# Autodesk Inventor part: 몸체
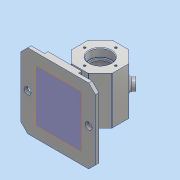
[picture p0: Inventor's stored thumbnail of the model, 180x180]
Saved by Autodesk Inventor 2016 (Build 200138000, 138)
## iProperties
Created: 2018-06
Part Number: 몸체
Material: 알루미늄 6061
Document SubType Name: Modeling
Designer: 605-11
Density: 2.7 g/cm^3
Appearance: 알루미늄 - 평지
Author: 605-11
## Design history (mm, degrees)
sketch "스케치1"
  geometry: L1 (30, -12.426)-(12.426, -30); L2 (12.426, -30)-(-12.426, -30); L3 (-12.426, -30)-(-30, -12.426); L4 (-30, -12.426)-(-30, 12.426); L5 (-30, 12.426)-(-12.426, 30); L6 (-12.426, 30)-(12.426, 30); L7 (12.426, 30)-(30, 12.426); L8 (30, 12.426)-(30, -12.426); L9 (0, 0)-(-12.426, 30); L10 (0, 0)-(0, 30); L11 (0, 0)-(12.426, 30); 1 further point
  constraints: 22 end point, 2 point on line, 1 coincident, 1 midpoint, 1 vertical, 1 vertical alignment, 17 other
  dimensions: "d0" = 60 distance between parallel lines of L8 L4; "d1" = 22.5 deg angle of L10 L9; "d2" = 45 deg angle of L11 L9
extrude "돌출1" new body sketch "스케치1" stored distance "d3" = 70; taper "d4" = 0 deg
sketch "스케치2"
  geometry: L1 (0, 35)-(16, 35); L2 (16, 35)-(16, 23.3); L3 (15.7, 23)-(0, 23); L4 (0, 23)-(0, 35); L5 (0, 23)-(14, 23); L6 (14, 23)-(14, 20); L7 (14, 20)-(0, 20); L8 (0, 20)-(0, 23); L9 (0, 20)-(22, 20); L10 (25, 17)-(25, -17); L11 (22, -20)-(0, -20); L12 (0, -20)-(0, 20); L13 (0, -20)-(14, -20); L14 (14, -20)-(14, -23); L15 (14, -23)-(0, -23); L16 (0, -23)-(0, -20); L17 (0, -23)-(15.7, -23); L18 (16, -23.3)-(16, -35); L19 (16, -35)-(0, -35); L20 (0, -35)-(0, -23); L21 (12.426, 35)-(-12.426, 35) reference; A1 r 0.3 centre (15.7, 23.3) between (15.7, 23) and (16, 23.3); A2 r 0.3 centre (15.7, -23.3) between (16, -23.3) and (15.7, -23); A3 r 3 centre (22, -17) between (22, -20) and (25, -17); A4 r 3 centre (22, 17) between (25, 17) and (22, 20); 6 further points
  constraints: 40 end point, 10 parallel, 8 point on circle, 8 point on line, 8 tangent, 5 horizontal, 5 perpendicular, 4 centre point, 2 equal radius, 1 coincident, 1 midpoint
  dimensions: "d5" = 12 distance of L1.end point (16, 23); "d6" = 16 distance of L1.start L1.end; "d7" = 3 distance of L5.end L6.end; "d8" = 14 distance of L3.end L5.end; "d9" = 40 distance of point (25, 20) point (25, -20); "d10" = 25 distance of L7.end point (25, 20); "d11" = 3 distance of L13.end L14.end; "d12" = 14 distance of L11.end L13.end; "d13" = 12 distance of point (16, -23) L18.end; "d14" = 16 distance of L15.end point (16, -23); "d15" = 0.3 radius of A1; "d16" = 3 radius of A3
revolve "회전1" sketch "스케치2" stored, may be unused: angle "d17" = 90 deg
chamfer "모따기1" distance "d18" = 1; stored, may be unused: second distance "d19" = 2, angle "d20" = 45 deg
sketch "스케치3"
  geometry: L1 (-24.853, 70)-(0, 70) reference; C1 r 8 at (-12.426, 35); 2 further points
  constraints: 1 centre point, 1 midpoint, 1 vertical alignment
  dimensions: "d21" = 35 distance from line of L1 C1.centre; "d22" = 16 diameter of C1
extrude "돌출2" join sketch "스케치3" distance "d23" = 7; taper "d24" = 0 deg
fillet "모깎기1" dims "d25" = 3
sketch "스케치4"
  geometry: C1 r 4 at (0, 0); 1 further point
  constraints: 1 centre point, 1 coincident
  dimensions: "d26" = 8 diameter of C1
extrude "돌출3" cut sketch "스케치4" stored distance "d27" = 7; taper "d28" = 0 deg; dims "d5" = 12, "d6" = 16, "d7" = 3, "d8" = 14, "d9" = 40, "d10" = 25, "d11" = 3, "d12" = 14, "d13" = 12, "d14" = 16, "d15" = 0.3, "d16" = 3, "d31" = 45 deg
chamfer "모따기2" distance "d29" = 1; stored, may be unused: second distance "d30" = 2, angle "d31" = 45 deg
sketch "스케치5" dims "d32" = 46
  geometry: 3 further points
  constraints: 2 vertical alignment, 1 coincident, 2 other
hole "구멍1" sketch "스케치5" at (0, 23) diameter "d33" = 3.242; stored, may be unused: countersink angle "d37" = 90 deg, drill point angle "d39" = 118 deg; dims "d34" = 8, "d35" = 4, "d36" = 2, "d38" = 10
fillet "모깎기2" dims "d43" = 1
node "작업 평면1"
sketch "스케치6"
  geometry: L1 (12.012, -35)-(-12.012, -35) reference; L2 (30, -35)-(30, 35) reference; L3 (-30, 35)-(-30, -35) reference; L4 (-12.012, 35)-(12.012, 35) reference; L5 (45, -55)-(-45, -55); L6 (-55, -45)-(-55, 45); L7 (-45, 55)-(45, 55); L8 (55, 45)-(55, -45); L9 (55, -55)-(-55, 55); L10 (-55, -55)-(55, 55); L11 (55, -45)-(45, -55); L12 (55, 45)-(45, 55); L13 (-45, 55)-(-55, 45); L14 (-55, -45)-(-45, -55); 1 further point
  constraints: 20 end point, 8 point on line, 2 midpoint, 2 parallel, 1 horizontal, 1 perpendicular
  dimensions: "d45" = 110 distance of L9.start L10.start; "d46" = 110 distance of L10.start L9.end; "d47" = 10 distance of L8.end L9.start; "d48" = 10 distance of L5.start L9.start (= d47); "d49" = 10 distance of L8.start L10.end (= d47); "d50" = 10 distance of L7.end L10.end (= d49); "d51" = 10 distance of L7.start L9.end (= d47); "d52" = 10 distance of L6.end L9.end (= d51); "d53" = 10 distance of L6.start L10.start (= d47); "d54" = 10 distance of L5.end L10.start (= d53)
extrude "돌출4" join sketch "스케치6" distance "d55" = 5; taper "d56" = 0 deg
sketch "스케치7"
  geometry: L1 (-25, 55)-(25, 55); L2 (25, 55)-(25, -55); L3 (25, -55)-(-25, -55); L4 (-25, -55)-(-25, 55); L5 (-25, 55)-(25, -55); L6 (25, 55)-(-25, -55); L7 (55, 45)-(55, -45) reference; 1 further point
  constraints: 12 end point, 2 midpoint, 2 parallel, 1 horizontal, 1 perpendicular
  dimensions: "d57" = 110 distance of L1.end L2.end; "d58" = 30 distance between parallel lines of L7 L2
extrude "돌출5" join sketch "스케치7" distance "d59" = 5; taper "d60" = 0 deg
sketch "스케치8"
  geometry: L1 (0, 19)-(0, -19); L2 (-5, 19)-(-5, -19); L3 (5, -19)-(5, 19); L4 (-55, 45)-(-55, -45) reference; L5 (45, -55)-(-45, -55) reference; A1 r 5 centre (0, 19) between (5, 19) and (-5, 19); A2 r 5 centre (0, -19) between (-5, -19) and (5, -19); 2 further points
  constraints: 8 end point, 4 point on circle, 4 tangent, 2 centre point, 1 midpoint, 1 parallel, 1 vertical
  dimensions: "d61" = 55 distance from line of L4 point (0, 0); "d62" = 38 distance of L1.start L1.end; "d63" = 55 distance from line of L5 point (0, 0); "d64" = 5 radius of A1
extrude "돌출6" join sketch "스케치8" stored distance "d65" = 5; taper "d66" = 0 deg
fillet "모깎기3" dims "d67" = 2
sketch "스케치9"
  geometry: L1 (-55, -45)-(-55, 45) reference; C1 r 5 at (-45, 0); 1 further point
  constraints: 1 centre point, 1 horizontal alignment
  dimensions: "d70" = 10 distance from line of L1 C1.centre; "d71" = 10 diameter of C1
extrude "돌출7" cut sketch "스케치9" stored distance "d72" = 5; taper "d73" = 0 deg
node "작업 평면2"
sketch "스케치10"
  geometry: L1 (-12.012, 35)-(12.012, 35) reference; 2 further points
  constraints: 1 coincident, 1 other
  dimensions: "d75" = 35 distance from line of point (0, 0) L1
feature "엠보싱1" sketch "스케치10" dims "d0" = 60, "d1" = 22.5 deg, "d2" = 45 deg, "d5" = 12, "d6" = 16, "d7" = 3, "d8" = 14, "d9" = 40, "d10" = 25, "d11" = 3, "d12" = 14, "d13" = 12, "d14" = 16, "d15" = 0.3, "d16" = 3, "d76" = 0.5, "d77" = 0
node "솔리드1"
pattern_circular "원형 패턴1" dims angle "d41" = 360 deg
mirror "대칭1"
mirror "대칭2"
other parameters: "d44" = -62, "d74" = 52.25
